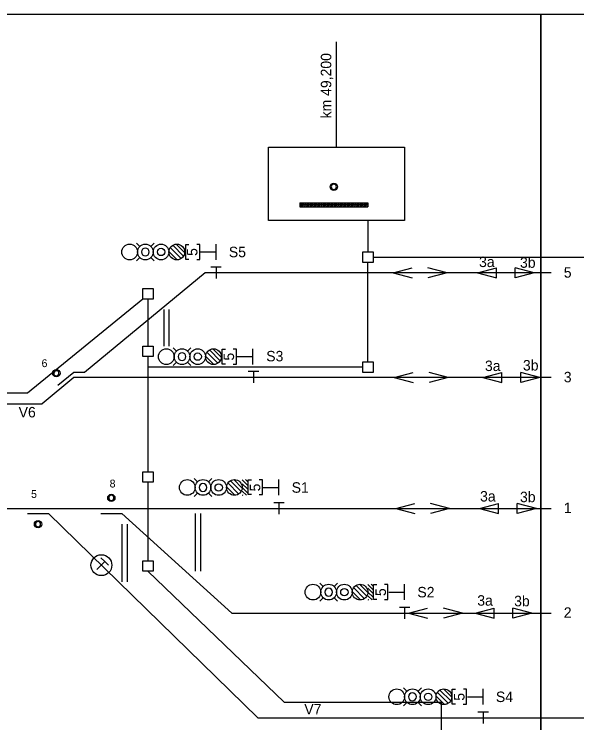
# Model space of a CAD drawing. Extents: x -1146 to 534, y 4 to 301.
# Drawn here: x -406.6 to -299.1, y 166 to 301.4 of the extents above; entities that cross this region are included whole.
import ezdxf

# ---------------------------------------------------------------- set-up
doc = ezdxf.new("R2010")
doc.units = 0
for name, color, linetype in [('formát tisku', 7, 'Continuous'), ('kabel', 7, 'Continuous'), ('koleje', 7, 'Continuous'), ('návěstidla', 7, 'Continuous'), ('popisy', 7, 'Continuous'), ('čd', 7, 'Continuous')]:
    doc.layers.add(name, color=color, linetype=linetype)

# ---------------------------------------------------------------- blocks, each defined once
blk = doc.blocks.new('_X21')
for p, q in [((-3.5, 1.45), (-3.25, 1.7)), ((-3.5, 1.627), (-3.427, 1.7)), ((-3.473, 1.3), (-3.073, 1.7)), ((-3.296, 1.3), (-2.896, 1.7)), ((-3.119, 1.3), (-2.719, 1.7)), ((-2.943, 1.3), (-2.543, 1.7)), ((-2.766, 1.3), (-2.366, 1.7)), ((-2.589, 1.3), (-2.189, 1.7)), ((-2.412, 1.3), (-2.012, 1.7)), ((-2.236, 1.3), (-1.836, 1.7)), ((-2.059, 1.3), (-1.659, 1.7)), ((-1.882, 1.3), (-1.482, 1.7)), ((-1.705, 1.3), (-1.305, 1.7)), ((-1.528, 1.3), (-1.128, 1.7)), ((-1.352, 1.3), (-0.952, 1.7)), ((-1.175, 1.3), (-0.775, 1.7)), ((-0.998, 1.3), (-0.598, 1.7)), ((-0.821, 1.3), (-0.421, 1.7)), ((-0.645, 1.3), (-0.245, 1.7)), ((-0.468, 1.3), (-0.068, 1.7)), ((-0.291, 1.3), (0.109, 1.7)), ((-0.114, 1.3), (0.286, 1.7)), ((0.063, 1.3), (0.463, 1.7)), ((0.239, 1.3), (0.639, 1.7)), ((0.416, 1.3), (0.816, 1.7)), ((0.593, 1.3), (0.993, 1.7)), ((0.77, 1.3), (1.17, 1.7)), ((0.946, 1.3), (1.346, 1.7)), ((1.123, 1.3), (1.523, 1.7)), ((1.3, 1.3), (1.7, 1.7)), ((1.477, 1.3), (1.877, 1.7)), ((1.654, 1.3), (2.054, 1.7)), ((1.83, 1.3), (2.23, 1.7)), ((2.007, 1.3), (2.407, 1.7)), ((2.184, 1.3), (2.584, 1.7)), ((2.361, 1.3), (2.761, 1.7)), ((2.537, 1.3), (2.937, 1.7)), ((2.714, 1.3), (3, 1.586)), ((2.891, 1.3), (3, 1.409))]:
    blk.add_line(p, q)
blk = doc.blocks.new('O4')
for p, q in [((-6.5, 0), (-6.5, 7)), ((-6.5, 7), (6.5, 7)), ((6.5, 7), (6.5, 0)), ((-3.5, 1.7), (-3.5, 1.3)), ((-3.5, 1.7), (3, 1.7)), ((3, 1.5), (-3.5, 1.5)), ((3, 1.7), (3, 1.3)), ((-3.5, 1.3), (3, 1.3)), ((6.5, 0), (-6.5, 0))]:
    blk.add_line(p, q)
for start, end in [(0, 180), (180, 0)]:
    blk.add_arc((-0.255, 3.226), 0.25, start, end)
blk.add_blockref('_X21', (0, 0))
blk = doc.blocks.new('NS16')
for p, q in [((-1.499, 0.6437), (-1.1298, 1.0129)), ((-1.4356, 0), (-0.4227, 1.0129)), ((-0.7285, 0), (0.2844, 1.0129)), ((-0.0214, 0), (0.9915, 1.0129)), ((0.6857, 0), (1.499, 0.8133)), ((1.3928, 0), (1.499, 0.1062))]:
    blk.add_line(p, q)
blk = doc.blocks.new('SB1')
for p, q in [((0, 1.08), (-1, 1.08)), ((1, 1.08), (0, 1.08)), ((0, 1.08), (0, -1.08))]:
    blk.add_line(p, q)
blk = doc.blocks.new('SB2')
for p, q in [((-0.03, 0.94), (-1.03, 0.94)), ((0.96, 0.94), (-0.04, 0.94)), ((-0.03, 0.94), (-0.03, -1.21))]:
    blk.add_line(p, q)
blk.add_circle((0, 0), 2)
blk = doc.blocks.new('PZ2')
for start, end in [(0, 180), (180, 0)]:
    blk.add_arc((0, 2), 0.5, start, end)

msp = doc.modelspace()

# ---------------------------------------------------------------- linework, layer by layer
for p, q in [((-305.96, 301.44), (-305.96, 292.55)), ((-382.5, 257), (-383.2, 257.7)), ((-380.5, 257), (-379.8, 257.7)), ((-376.25, 257.3), (-374.2, 255.2)), ((-375.6, 257.5), (-374, 255.9)), ((-368, 254.5), (-368, 257.5)), ((-377, 256.1), (-375.4, 254.5)), ((-376.7, 256.8), (-374.7, 254.8)), ((-371, 256), (-368, 256)), ((-382.5, 255), (-383.2, 254.3)), ((-380.5, 255), (-379.8, 254.3)), ((-334.2, 252), (-330.57, 252.95)), ((-334.2, 252), (-330.57, 251.05)), ((-323.9, 252), (-327.53, 252.95)), ((-323.9, 252), (-327.53, 251.05)), ((-318.09, 252), (-314.46, 252.95)), ((-318.09, 252), (-314.46, 251.05)), ((-307.26, 252), (-310.89, 252.95)), ((-307.26, 252), (-310.89, 251.05)), ((-375.5, 237), (-376.2, 237.7)), ((-373.5, 237), (-372.8, 237.7)), ((-369.25, 237.3), (-367.2, 235.2)), ((-368.6, 237.5), (-367, 235.9)), ((-361, 234.5), (-361, 237.5)), ((-370, 236.1), (-368.4, 234.5)), ((-369.7, 236.8), (-367.7, 234.8)), ((-364, 236), (-361, 236)), ((-375.5, 235), (-376.2, 234.3)), ((-373.5, 235), (-372.8, 234.3)), ((-333.96, 232), (-330.33, 232.95)), ((-323.66, 232), (-327.29, 232.95)), ((-317.03, 232), (-313.4, 232.95)), ((-306.2, 232), (-309.83, 232.95)), ((-333.96, 232), (-330.33, 231.05)), ((-323.66, 232), (-327.29, 231.05)), ((-317.03, 232), (-313.4, 231.05)), ((-306.2, 232), (-309.83, 231.05)), ((-371.5, 212), (-372.2, 212.7)), ((-369.5, 212), (-368.8, 212.7)), ((-365.7, 211.8), (-363.7, 209.8)), ((-365.25, 212.3), (-363.2, 210.2)), ((-364.6, 212.5), (-363, 210.9)), ((-356, 209.5), (-356, 212.5)), ((-371.5, 210), (-372.2, 209.3)), ((-369.5, 210), (-368.8, 209.3)), ((-366, 211.1), (-364.4, 209.5)), ((-359, 211), (-356, 211)), ((-333.7, 207), (-330.06, 207.95)), ((-323.4, 207), (-327.03, 207.95)), ((-317.67, 207), (-314.04, 207.95)), ((-306.84, 207), (-310.47, 207.95)), ((-333.7, 207), (-330.06, 206.05)), ((-323.4, 207), (-327.03, 206.05)), ((-317.67, 207), (-314.04, 206.05)), ((-306.84, 207), (-310.47, 206.05)), ((-347.5, 192), (-348.2, 192.7)), ((-345.5, 192), (-344.8, 192.7)), ((-341.25, 192.3), (-339.2, 190.2)), ((-340.6, 192.5), (-339, 190.9)), ((-332, 189.5), (-332, 192.5)), ((-342, 191.1), (-340.4, 189.5)), ((-341.7, 191.8), (-339.7, 189.8)), ((-335, 191), (-332, 191)), ((-347.5, 190), (-348.2, 189.3)), ((-345.5, 190), (-344.8, 189.3)), ((-331.26, 187), (-327.62, 187.95)), ((-331.26, 187), (-327.62, 186.05)), ((-320.96, 187), (-324.59, 187.95)), ((-320.96, 187), (-324.59, 186.05)), ((-318.53, 187), (-314.9, 187.95)), ((-318.53, 187), (-314.9, 186.05)), ((-307.69, 187), (-311.33, 187.95)), ((-307.69, 187), (-311.33, 186.05)), ((-331.5, 172), (-332.2, 172.7)), ((-329.5, 172), (-328.8, 172.7)), ((-325.25, 172.3), (-323.2, 170.2)), ((-324.6, 172.5), (-323, 170.9)), ((-317, 169.5), (-317, 172.5)), ((-326, 171.1), (-324.4, 169.5)), ((-325.7, 171.8), (-323.7, 169.8)), ((-320, 171), (-317, 171)), ((-331.5, 170), (-332.2, 169.3)), ((-329.5, 170), (-328.8, 169.3))]:
    msp.add_line(p, q)
for centre, radius in [((-345.51, 268.45), 0.7), ((-384.5, 256), 1.5), ((-381.5, 256), 1.5), ((-378.5, 256), 1.5), ((-375.5, 256), 1.5), ((-378.5, 256), 0.7), ((-377.5, 236), 1.5), ((-374.5, 236), 1.5), ((-371.5, 236), 1.5), ((-368.5, 236), 1.5), ((-371.5, 236), 0.7), ((-398.5, 232.83), 0.7), ((-373.5, 211), 1.5), ((-370.5, 211), 1.5), ((-367.5, 211), 1.5), ((-367.5, 211), 0.7), ((-364.5, 211), 1.5), ((-388, 209), 0.7), ((-402, 204), 0.7), ((-349.5, 191), 1.5), ((-346.5, 191), 1.5), ((-343.5, 191), 1.5), ((-340.5, 191), 1.5), ((-343.5, 191), 0.7), ((-333.5, 171), 1.5), ((-330.5, 171), 1.5), ((-327.5, 171), 1.5), ((-324.5, 171), 1.5), ((-327.5, 171), 0.7)]:
    msp.add_circle(centre, radius)
for centre, start, end in [((-381.5, 256), 90, 270), ((-381.5, 256), 270, 90), ((-374.5, 236), 90, 270), ((-374.5, 236), 270, 90), ((-370.5, 211), 90, 270), ((-370.5, 211), 270, 90), ((-346.5, 191), 90, 270), ((-346.5, 191), 270, 90), ((-330.5, 171), 90, 270), ((-330.5, 171), 270, 90)]:
    msp.add_arc(centre, 0.75, start, end)
at = {"layer": 'formát tisku'}
for points in [[(-515.96, 301.44), (-305.96, 301.44), (-305.96, 4.44), (-515.96, 4.44)], [(-305.96, 301.44), (-95.96, 301.44), (-95.96, 4.44), (-305.96, 4.44)]]:
    msp.add_lwpolyline(points, close=True, dxfattribs=at)
at = {"layer": 'kabel'}
for p, q in [((-339, 262), (-339, 256)), ((-338, 255), (-272, 255)), ((-339, 235), (-339, 254)), ((-381, 247), (-381, 238)), ((-381, 236), (-381, 214)), ((-340, 234), (-381, 234)), ((-381, 212), (-381, 197))]:
    msp.add_line(p, q, dxfattribs=at)
for points in [[(-340, 256), (-338, 256), (-338, 254), (-340, 254)], [(-382, 249), (-380, 249), (-380, 247), (-382, 247)], [(-382, 238), (-380, 238), (-380, 236), (-382, 236)], [(-340, 235), (-338, 235), (-338, 233), (-340, 233)], [(-382, 214), (-380, 214), (-380, 212), (-382, 212)], [(-382, 197), (-380, 197), (-380, 195), (-382, 195)]]:
    msp.add_lwpolyline(points, close=True, dxfattribs=at)
for points in [[(-382, 247), (-404, 229), (-418, 229)], [(-381, 195), (-355, 170), (-325, 170), (-325, 150), (-333.33, 138.55)]]:
    msp.add_lwpolyline(points, dxfattribs=at)
at = {"layer": 'koleje'}
for p, q in [((-370.07, 252), (-393.14, 233)), ((-304, 252), (-370.07, 252)), ((-378, 245), (-378, 238)), ((-377, 245), (-377, 238)), ((-395.14, 233), (-398.23, 230.46)), ((-393.14, 233), (-395.14, 233)), ((-395.14, 232), (-401.21, 227)), ((-304, 232), (-395.14, 232)), ((-432.14, 227), (-401.21, 227)), ((-404, 206), (-400, 206)), ((-400, 206), (-360, 167)), ((-390, 206), (-386, 206)), ((-386, 206), (-365, 187)), ((-372, 206), (-372, 195)), ((-371, 206), (-371, 195)), ((-386, 204), (-386, 193)), ((-385, 204), (-385, 193)), ((-365, 187), (-304, 187)), ((-360, 167), (-251, 167))]:
    msp.add_line(p, q, dxfattribs=at)
msp.add_lwpolyline([(-736, 107), (-615, 107), (-488, 207), (-304, 207)], dxfattribs=at)
at = {"layer": 'popisy'}
msp.add_line((-345, 276), (-345, 296.15), dxfattribs=at)
at = {"layer": 'čd'}
for p, q in [((-373.8, 254.56), (-373.8, 257.41)), ((-373.8, 257.41), (-373.18, 257.41)), ((-371.07, 257.41), (-371.7, 257.41)), ((-371.07, 254.56), (-371.07, 257.41)), ((-373.18, 254.56), (-373.8, 254.56)), ((-371.7, 254.56), (-371.07, 254.56)), ((-314.46, 251.05), (-314.46, 252.95)), ((-310.89, 251.05), (-310.89, 252.95)), ((-307.26, 252.01), (-307.26, 251.99)), ((-366.84, 234.57), (-366.84, 237.43)), ((-366.84, 237.43), (-366.22, 237.43)), ((-364.11, 237.43), (-364.73, 237.43)), ((-364.11, 234.57), (-364.11, 237.43)), ((-366.21, 234.57), (-366.84, 234.57)), ((-364.74, 234.57), (-364.11, 234.57)), ((-313.4, 231.05), (-313.4, 232.95)), ((-309.83, 231.05), (-309.83, 232.95)), ((-361.88, 209.63), (-361.88, 212.49)), ((-361.88, 212.49), (-361.26, 212.49)), ((-359.15, 212.49), (-359.77, 212.49)), ((-359.15, 209.63), (-359.15, 212.49)), ((-361.25, 209.63), (-361.88, 209.63)), ((-359.78, 209.63), (-359.15, 209.63)), ((-314.04, 206.05), (-314.04, 207.95)), ((-310.47, 206.05), (-310.47, 207.95)), ((-337.92, 189.62), (-337.92, 192.48)), ((-337.92, 192.48), (-337.3, 192.48)), ((-335.19, 192.48), (-335.81, 192.48)), ((-335.19, 189.62), (-335.19, 192.48)), ((-337.29, 189.62), (-337.92, 189.62)), ((-335.82, 189.62), (-335.19, 189.62)), ((-314.9, 186.05), (-314.9, 187.95)), ((-311.33, 186.05), (-311.33, 187.95)), ((-322.89, 169.61), (-322.89, 172.46)), ((-322.89, 172.46), (-322.27, 172.46)), ((-320.16, 172.46), (-320.78, 172.46)), ((-320.16, 169.61), (-320.16, 172.46)), ((-322.26, 169.61), (-322.89, 169.61)), ((-320.79, 169.61), (-320.16, 169.61))]:
    msp.add_line(p, q, dxfattribs=at)

# ---------------------------------------------------------------- block references
at = {"layer": 'návěstidla', "rotation": -90.00000000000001}
for p in [(-363, 211), (-339, 191)]:
    msp.add_blockref('NS16', p, dxfattribs=at)
at = {"layer": 'čd', "xscale": 2, "yscale": 2}
msp.add_blockref('O4', (-345, 262), dxfattribs=at)
at = {"layer": 'čd'}
for name, p in [('SB1', (-368, 252)), ('SB1', (-360.86, 232.1)), ('PZ2', (-388, 207)), ('SB1', (-356, 207)), ('SB1', (-332, 187)), ('SB1', (-317, 167))]:
    msp.add_blockref(name, p, dxfattribs=at)
for name, p, rotation in [('PZ2', (-397.23, 231.28), 39.47245984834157), ('PZ2', (-402, 206), 180), ('SB2', (-389.9, 196.15), -44.274775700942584)]:
    msp.add_blockref(name, p, dxfattribs=dict(at, rotation=rotation))

# ---------------------------------------------------------------- texts
for s, p in [('6', (-401.32, 234)), ('8', (-388.32, 211)), ('5', (-403.32, 209))]:
    msp.add_text(s, height=1.5).set_placement(p)
at = {"layer": 'popisy'}
for s, p in [('km 49,200', (-346, 281.52)), ('5', (-371.56, 255.25)), ('5', (-364.56, 235.25)), ('5', (-359.56, 210.25)), ('5', (-335.56, 190.25)), ('5', (-320.56, 170.25))]:
    msp.add_text(s, height=2, rotation=90, dxfattribs=at).set_placement(p)
for s, p in [('S5', (-365.56, 255)), ('3a', (-317.78, 253.12)), ('3b', (-309.96, 252.98)), ('5', (-301.6, 251.1)), ('S3', (-358.42, 235.1)), ('3a', (-316.65, 233.25)), ('3b', (-309.4, 233.35)), ('3', (-301.6, 231.1)), ('V6', (-405.7, 224.39)), ('S1', (-353.56, 210)), ('3a', (-317.59, 208.32)), ('3b', (-309.96, 208.19)), ('1', (-301.6, 206.1)), ('S2', (-329.56, 190)), ('3a', (-318.12, 188.41)), ('3b', (-311.08, 188.3)), ('2', (-301.6, 186.1)), ('S4', (-314.56, 170)), ('V7', (-351.15, 167.62))]:
    msp.add_text(s, height=2, dxfattribs=at).set_placement(p)

doc.saveas('drawing.dxf')
